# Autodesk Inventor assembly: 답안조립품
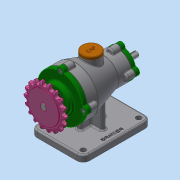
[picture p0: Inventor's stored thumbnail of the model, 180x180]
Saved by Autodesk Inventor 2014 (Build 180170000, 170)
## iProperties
Created: 2020-12
Part Number: 답안조립품
Document SubType Name: Assembly
Designer: net
Author: net
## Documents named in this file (15)
- C:\Users\net\Desktop\701206V1037\답안조립품.iam
- C:\Users\net\Desktop\701206V1037\본체.ipt
- C:\Users\net\Desktop\701206V1037\개스킷 A.ipt
- C:\Users\net\Desktop\701206V1037\개스킷 B.ipt
- C:\Users\net\Desktop\701206V1037\뒤커버.ipt
- C:\Users\net\Desktop\701206V1037\마개.ipt
- C:\Users\net\Desktop\701206V1037\베어링 6200.ipt
- C:\Users\net\Desktop\701206V1037\베어링 6203.ipt
- C:\Users\net\Desktop\701206V1037\볼트 M5.ipt
- C:\Users\net\Desktop\701206V1037\스프로킷.ipt
- C:\Users\net\Desktop\701206V1037\앞커버.ipt
- C:\Users\net\Desktop\701206V1037\오일 실 10 20 7.ipt
- C:\Users\net\Desktop\701206V1037\오일 실 17 30 8.ipt
- C:\Users\net\Desktop\701206V1037\축.ipt
- C:\Users\net\Desktop\701206V1037\키 4x4x14.ipt
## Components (2 placed, 2 different names)
1. 개스킷 A:1 — 각도:4
2. 개스킷 B:1
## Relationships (1: Angle 1)
- 각도:4 [Angle]: 개스킷 A:1
